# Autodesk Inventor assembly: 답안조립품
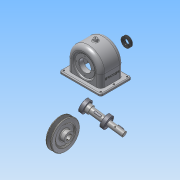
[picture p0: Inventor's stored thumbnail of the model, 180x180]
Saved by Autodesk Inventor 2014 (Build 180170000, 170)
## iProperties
Created: 2015-09
Part Number: 답안조립품
Document SubType Name: Assembly
Designer: 29
Author: 29
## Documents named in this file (8)
- C:\Users\29\Desktop\450907V1007\답안조립품.iam
- C:\Users\29\Desktop\450907V1007\본체.ipt
- C:\Users\29\Desktop\450907V1007\축.ipt
- C:\Users\29\Desktop\450907V1007\키 - 5 x 5 x 18.ipt
- C:\Users\29\Desktop\450907V1007\키 - 6 x 6 x 22.ipt
- C:\Users\29\Desktop\450907V1007\베어링 6203.ipt
- C:\Users\29\Desktop\450907V1007\오일 실 17 32 8.ipt
- C:\Users\29\Desktop\450907V1007\V-벨트풀리.ipt
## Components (1 placed, 1 different names)
1. V-벨트풀리:1
